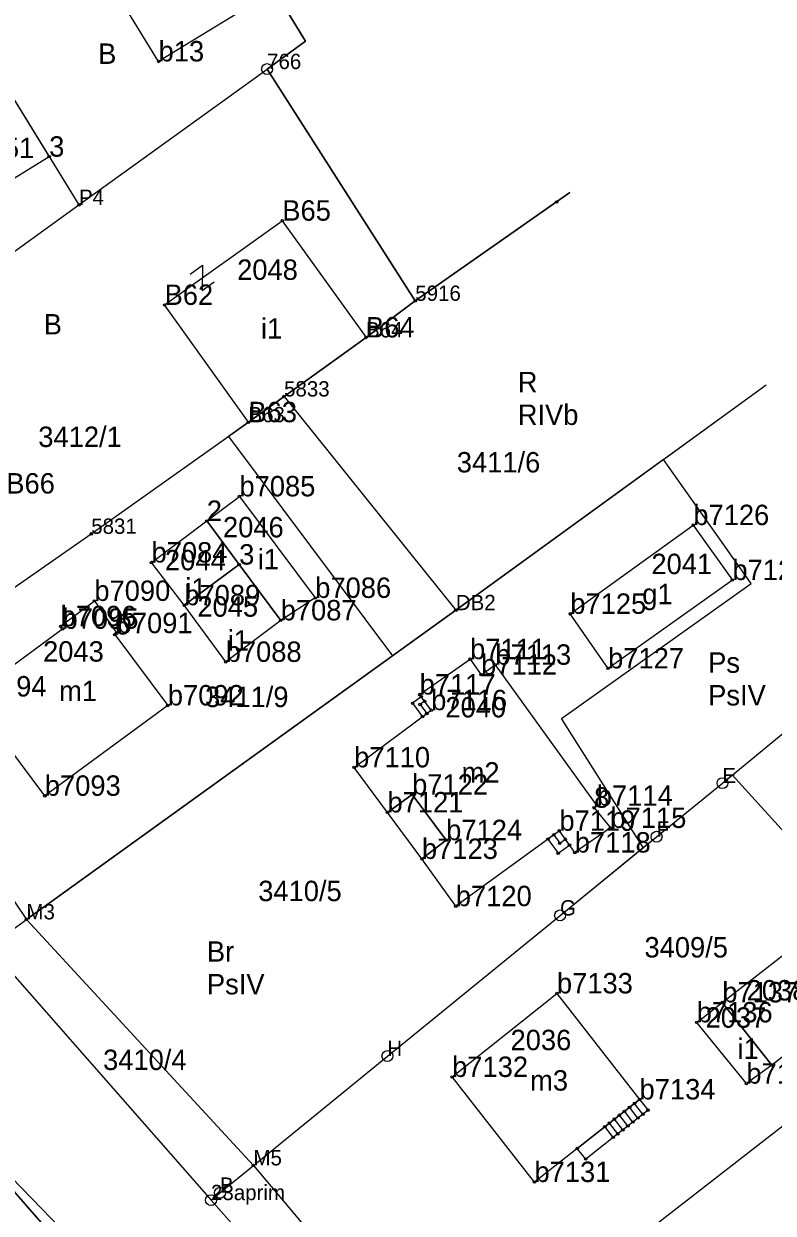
# Model space of a CAD drawing. Extents: x 7492083 to 7492670, y 5466693 to 5467065.
# Drawn here: x 7492206.8 to 7492261.9, y 5466933.4 to 5467020.8 of the extents above; entities that cross this region are included whole.
import ezdxf

# ---------------------------------------------------------------- set-up
doc = ezdxf.new("R2010")
doc.units = 0
for name, color, linetype in [('202-punkt graniczny', 7, 'Continuous'), ('202-punkt graniczny-Atr103', 7, 'Continuous'), ('203-punkt graniczny', 7, 'Continuous'), ('203-punkt graniczny-Atr103', 7, 'Continuous'), ('209-oznaczenie konturu klasyfikacyjnego', 7, 'Continuous'), ('210-oznaczenie konturu użytku gruntowego', 7, 'Continuous'), ('211-numer działki ewidencyjnej', 7, 'Continuous'), ('217-kontur klasyfikacyjny', 7, 'Continuous'), ('218-kontur użytku gruntowego', 7, 'Continuous'), ('219-działka ewidencyjna', 7, 'Continuous'), ('312-budynek ewidencyjny', 7, 'Continuous'), ('312-oznaczenie budynku ewidencyjnego', 7, 'Continuous'), ('312-oznaczenie budynku ewidencyjnego-Atr117', 7, 'Continuous'), ('352-schody', 7, 'Continuous'), ('991-Przehaczenie', 7, 'Continuous'), ('blok - nawis', 7, 'Continuous'), ('Punkt budynku', 7, 'Continuous'), ('Punkt budynku-Atr103', 7, 'Continuous'), ('Punkt budynku-Atr104', 7, 'Continuous')]:
    doc.layers.add(name, color=color, linetype=linetype)

# ---------------------------------------------------------------- blocks, each defined once
blk = doc.blocks.new('203')
blk.add_circle((0, 0), 0.09)
blk = doc.blocks.new('202')
blk.add_circle((0, 0), 0.4)
blk = doc.blocks.new('PUNKTBUD')
blk.add_circle((0, 0), 0.09)
blk = doc.blocks.new('991')
for p, q in [((-0.55, 0.75), (0.55, 0.75)), ((0.55, 0.75), (-0.55, -0.75)), ((-0.55, -0.75), (0.55, -0.75))]:
    blk.add_line(p, q)

msp = doc.modelspace()

# ---------------------------------------------------------------- linework, layer by layer
at = {"layer": '217-kontur klasyfikacyjny'}
for points in [[(7492215.82, 5467038.58), (7492227.5, 5467019.53)], [(7492227.5, 5467019.53), (7492224.67, 5467017.48)], [(7492224.67, 5467017.48), (7492235.56, 5467000.45)], [(7492246.921, 5467008.402), (7492245.94, 5467007.72)], [(7492245.94, 5467007.72), (7492235.56, 5467000.45)], [(7492235.56, 5467000.45), (7492231.94, 5466997.76)], [(7492231.94, 5466997.76), (7492225.92, 5466993.42)], [(7492253.8, 5466988.8), (7492261.338, 5466994.271)], [(7492225.92, 5466993.42), (7492223.3, 5466991.53)], [(7492223.3, 5466991.53), (7492221.84, 5466990.49)], [(7492221.84, 5466990.49), (7492233.88, 5466974.36)], [(7492253.8, 5466988.8), (7492238.54, 5466977.72)], [(7492260.25, 5466979.69), (7492253.8, 5466988.8)], [(7492246.3, 5466969.77), (7492260.25, 5466979.69)], [(7492238.54, 5466977.72), (7492233.88, 5466974.36)], [(7492233.88, 5466974.36), (7492206.99, 5466955)], [(7492252.31, 5466960.27), (7492246.3, 5466969.77)], [(7492258.13, 5466965.01), (7492258.85, 5466965.61)], [(7492258.85, 5466965.61), (7492266.79, 5466956.88)], [(7492253.29, 5466961.07), (7492258.13, 5466965.01)], [(7492246.2, 5466955.29), (7492252.31, 5466960.27)], [(7492252.31, 5466960.27), (7492253.29, 5466961.07)], [(7492233.51, 5466944.96), (7492246.2, 5466955.29)], [(7492206.99, 5466955), (7492223.67, 5466936.92)], [(7492223.67, 5466936.92), (7492233.51, 5466944.96)]]:
    msp.add_lwpolyline(points, dxfattribs=at)
at = {"layer": '218-kontur użytku gruntowego'}
for points in [[(7492227.5, 5467019.53), (7492215.82, 5467038.58)], [(7492224.67, 5467017.48), (7492227.5, 5467019.53)], [(7492235.56, 5467000.45), (7492224.67, 5467017.48)], [(7492246.921, 5467008.402), (7492245.94, 5467007.72)], [(7492245.94, 5467007.72), (7492235.56, 5467000.45)], [(7492235.56, 5467000.45), (7492231.94, 5466997.76)], [(7492231.94, 5466997.76), (7492225.92, 5466993.42)], [(7492253.8, 5466988.8), (7492261.338, 5466994.271)], [(7492225.92, 5466993.42), (7492223.3, 5466991.53)], [(7492223.3, 5466991.53), (7492221.84, 5466990.49)], [(7492221.84, 5466990.49), (7492233.88, 5466974.36)], [(7492253.8, 5466988.8), (7492238.54, 5466977.72)], [(7492260.25, 5466979.69), (7492253.8, 5466988.8)], [(7492246.3, 5466969.77), (7492260.25, 5466979.69)], [(7492238.54, 5466977.72), (7492233.88, 5466974.36)], [(7492233.88, 5466974.36), (7492206.99, 5466955)], [(7492195.51, 5466972.02), (7492206.99, 5466955)], [(7492252.31, 5466960.27), (7492246.3, 5466969.77)], [(7492258.13, 5466965.01), (7492258.85, 5466965.61)], [(7492258.85, 5466965.61), (7492266.79, 5466956.88)], [(7492253.29, 5466961.07), (7492258.13, 5466965.01)], [(7492246.2, 5466955.29), (7492252.31, 5466960.27)], [(7492252.31, 5466960.27), (7492253.29, 5466961.07)], [(7492233.51, 5466944.96), (7492246.2, 5466955.29)], [(7492206.99, 5466955), (7492223.67, 5466936.92)], [(7492223.67, 5466936.92), (7492233.51, 5466944.96)], [(7492219.52, 5466919.65), (7492198.51, 5466943.63)], [(7492223.67, 5466936.92), (7492237.56, 5466920.41)]]:
    msp.add_lwpolyline(points, dxfattribs=at)
at = {"layer": '219-działka ewidencyjna'}
for points in [[(7492203.92, 5467018.7), (7492210.85, 5467007.5)], [(7492210.85, 5467007.5), (7492224.67, 5467017.48)], [(7492224.67, 5467017.48), (7492235.56, 5467000.45)], [(7492245.94, 5467007.72), (7492246.921, 5467008.402)], [(7492185.94, 5466989.5), (7492210.85, 5467007.5)], [(7492235.56, 5467000.45), (7492245.94, 5467007.72)], [(7492231.94, 5466997.76), (7492235.56, 5467000.45)], [(7492225.92, 5466993.42), (7492231.94, 5466997.76)], [(7492238.54, 5466977.72), (7492261.338, 5466994.271)], [(7492223.3, 5466991.53), (7492225.92, 5466993.42)], [(7492225.92, 5466993.42), (7492238.54, 5466977.72)], [(7492211.75, 5466983.33), (7492223.3, 5466991.53)], [(7492195.51, 5466972.02), (7492211.75, 5466983.33)], [(7492206.99, 5466955), (7492238.54, 5466977.72)], [(7492195.51, 5466972.02), (7492206.99, 5466955)], [(7492258.13, 5466965.01), (7492264.25, 5466970.06)], [(7492253.29, 5466961.07), (7492258.13, 5466965.01)], [(7492246.2, 5466955.29), (7492253.29, 5466961.07)], [(7492233.51, 5466944.96), (7492246.2, 5466955.29)], [(7492204.2, 5466952.99), (7492206.99, 5466955)], [(7492206.99, 5466955), (7492223.67, 5466936.92)], [(7492204.2, 5466952.99), (7492220.55, 5466934.37)], [(7492237.56, 5466920.41), (7492278.95, 5466952.56)], [(7492223.67, 5466936.92), (7492233.51, 5466944.96)], [(7492198.51, 5466943.63), (7492260.93, 5466879.15)], [(7492198.51, 5466943.63), (7492219.52, 5466919.65)], [(7492221.21, 5466934.91), (7492223.67, 5466936.92)], [(7492223.67, 5466936.92), (7492237.56, 5466920.41)], [(7492220.55, 5466934.37), (7492221.21, 5466934.91)], [(7492220.55, 5466934.37), (7492234.8, 5466918.26)]]:
    msp.add_lwpolyline(points, dxfattribs=at)
at = {"layer": '312-budynek ewidencyjny'}
for points in [[(7492216.7, 5467018.04), (7492211.32, 5467026.81)], [(7492223.52, 5467022.2), (7492216.7, 5467018.04)], [(7492203.92, 5467018.7), (7492208.66, 5467011.04)], [(7492208.66, 5467011.04), (7492202.65, 5467007.34)], [(7492217.14, 5467000.15), (7492225.79, 5467006.34)], [(7492225.79, 5467006.34), (7492231.94, 5466997.76)], [(7492223.3, 5466991.53), (7492217.14, 5467000.15)], [(7492231.94, 5466997.76), (7492223.3, 5466991.53)], [(7492220.24, 5466984.28), (7492222.64, 5466986.08)], [(7492222.64, 5466986.08), (7492228.21, 5466978.62)], [(7492216.18, 5466981.22), (7492220.24, 5466984.28)], [(7492220.24, 5466984.28), (7492222.62, 5466981.07)], [(7492222.62, 5466981.07), (7492220.24, 5466984.28)], [(7492246.95, 5466977.45), (7492255.99, 5466983.97)], [(7492255.99, 5466983.97), (7492258.86, 5466979.93)], [(7492218.59, 5466978.08), (7492216.18, 5466981.22)], [(7492222.62, 5466981.07), (7492218.59, 5466978.08)], [(7492218.59, 5466978.08), (7492222.62, 5466981.07)], [(7492222.62, 5466981.07), (7492225.67, 5466976.97)], [(7492225.67, 5466976.97), (7492222.62, 5466981.07)], [(7492258.86, 5466979.93), (7492249.73, 5466973.44)], [(7492228.21, 5466978.62), (7492225.67, 5466976.97)], [(7492209.5, 5466976.54), (7492211.98, 5466978.4)], [(7492211.98, 5466978.4), (7492213.62, 5466976.03)], [(7492221.63, 5466973.92), (7492218.59, 5466978.08)], [(7492225.67, 5466976.97), (7492221.63, 5466973.92)], [(7492249.73, 5466973.44), (7492246.95, 5466977.45)], [(7492202.89, 5466971.38), (7492209.64, 5466976.35)], [(7492209.64, 5466976.35), (7492209.5, 5466976.54)], [(7492213.62, 5466976.03), (7492213.48, 5466975.93)], [(7492213.48, 5466975.93), (7492217.38, 5466970.72)], [(7492235.88, 5466971.52), (7492239.59, 5466974.12)], [(7492239.59, 5466974.12), (7492240.4, 5466972.98)], [(7492240.4, 5466972.98), (7492241.44, 5466973.71)], [(7492241.44, 5466973.71), (7492248.9, 5466963.35)], [(7492208.34, 5466964.08), (7492202.89, 5466971.38)], [(7492236.73, 5466970.37), (7492235.88, 5466971.52)], [(7492217.38, 5466970.72), (7492208.34, 5466964.08)], [(7492231.07, 5466966.17), (7492236.73, 5466970.37)], [(7492233.52, 5466962.86), (7492231.07, 5466966.17)], [(7492235.33, 5466964.17), (7492233.52, 5466962.86)], [(7492237.83, 5466960.82), (7492235.33, 5466964.17)], [(7492248.9, 5466963.35), (7492248.7, 5466963.2)], [(7492248.7, 5466963.2), (7492249.9, 5466961.72)], [(7492246.15, 5466961.51), (7492238.54, 5466955.97)], [(7492247.28, 5466959.91), (7492246.15, 5466961.51)], [(7492249.9, 5466961.72), (7492247.28, 5466959.91)], [(7492236.05, 5466959.44), (7492237.83, 5466960.82)], [(7492238.54, 5466955.97), (7492236.05, 5466959.44)], [(7492258.12, 5466948.9), (7492263.18, 5466952.83)], [(7492238.27, 5466943.42), (7492245.97, 5466949.56)], [(7492245.97, 5466949.56), (7492252.04, 5466941.77)], [(7492256.24, 5466947.43), (7492258.12, 5466948.9)], [(7492258.12, 5466948.9), (7492261.75, 5466944.29)], [(7492261.75, 5466944.29), (7492258.12, 5466948.9)], [(7492266.73, 5466948.13), (7492261.75, 5466944.29)], [(7492259.89, 5466942.93), (7492256.24, 5466947.43)], [(7492261.75, 5466944.29), (7492259.89, 5466942.93)], [(7492244.32, 5466935.7), (7492238.27, 5466943.42)], [(7492252.04, 5466941.77), (7492244.32, 5466935.7)]]:
    msp.add_lwpolyline(points, dxfattribs=at)
at = {"layer": '352-schody'}
for p, q in [((7492236, 5466971.36), (7492235.36, 5466970.88)), ((7492235.36, 5466970.88), (7492236.09, 5466969.89)), ((7492236.24, 5466971.03), (7492235.92, 5466970.79)), ((7492235.92, 5466970.79), (7492236.41, 5466970.13)), ((7492236.73, 5466970.37), (7492236, 5466971.36)), ((7492236.09, 5466969.89), (7492236.73, 5466970.37)), ((7492246.15, 5466961.51), (7492245.31, 5466960.9)), ((7492245.73, 5466961.21), (7492246.17, 5466960.59)), ((7492246.89, 5466960.46), (7492246.15, 5466961.51)), ((7492245.31, 5466960.9), (7492246.06, 5466959.86)), ((7492246.06, 5466959.86), (7492246.89, 5466960.46)), ((7492246.17, 5466960.59), (7492246.59, 5466960.89)), ((7492247.46, 5466938.17), (7492252.04, 5466941.77)), ((7492251.92, 5466940.4), (7492251.3, 5466941.19)), ((7492252.29, 5466940.69), (7492251.67, 5466941.48)), ((7492252.04, 5466941.77), (7492252.66, 5466940.98)), ((7492252.66, 5466940.98), (7492250.11, 5466938.98)), ((7492250.81, 5466939.53), (7492250.19, 5466940.32)), ((7492251.18, 5466939.82), (7492250.56, 5466940.61)), ((7492251.55, 5466940.11), (7492250.93, 5466940.9)), ((7492250.11, 5466938.98), (7492249.49, 5466939.77)), ((7492250.44, 5466939.24), (7492249.82, 5466940.03)), ((7492250.11, 5466938.98), (7492248.08, 5466937.39)), ((7492248.08, 5466937.39), (7492247.46, 5466938.17))]:
    msp.add_line(p, q, dxfattribs=at)
at = {"layer": 'blok - nawis'}
msp.add_lwpolyline([(7492233.52, 5466962.86), (7492235.33, 5466964.17), (7492237.83, 5466960.82), (7492236.05, 5466959.44)], close=True, dxfattribs=at)

# ---------------------------------------------------------------- block references
at = {"layer": '202-punkt graniczny'}
for p in [(7492224.67, 5467017.48), (7492258.13, 5466965.01), (7492253.29, 5466961.07), (7492246.2, 5466955.29), (7492233.51, 5466944.96), (7492221.21, 5466934.91), (7492220.55, 5466934.37)]:
    msp.add_blockref('202', p, dxfattribs=at)
at = {"layer": '203-punkt graniczny'}
for p in [(7492210.85, 5467007.5), (7492245.94, 5467007.72), (7492235.56, 5467000.45), (7492231.94, 5466997.76), (7492225.92, 5466993.42), (7492223.3, 5466991.53), (7492211.75, 5466983.33), (7492238.54, 5466977.72), (7492206.99, 5466955), (7492223.67, 5466936.92)]:
    msp.add_blockref('203', p, dxfattribs=at)
at = {"layer": '991-Przehaczenie', "rotation": 35.586}
msp.add_blockref('991', (7492219.91, 5467002.13), dxfattribs=at)
at = {"layer": 'Punkt budynku'}
for p in [(7492216.7, 5467018.04), (7492208.66, 5467011.04), (7492225.79, 5467006.34), (7492217.14, 5467000.15), (7492231.94, 5466997.76), (7492223.3, 5466991.53), (7492222.64, 5466986.08), (7492220.24, 5466984.28), (7492255.99, 5466983.97), (7492216.18, 5466981.22), (7492222.62, 5466981.07), (7492258.86, 5466979.93), (7492228.21, 5466978.62), (7492211.98, 5466978.4), (7492218.59, 5466978.08), (7492225.67, 5466976.97), (7492246.95, 5466977.45), (7492209.5, 5466976.54), (7492209.64, 5466976.35), (7492213.48, 5466975.93), (7492213.62, 5466976.03), (7492221.63, 5466973.92), (7492239.59, 5466974.12), (7492241.44, 5466973.71), (7492249.73, 5466973.44), (7492240.4, 5466972.98), (7492217.38, 5466970.72), (7492235.36, 5466970.88), (7492235.88, 5466971.52), (7492235.92, 5466970.79), (7492236, 5466971.36), (7492236.24, 5466971.03), (7492236.09, 5466969.89), (7492236.41, 5466970.13), (7492236.73, 5466970.37), (7492231.07, 5466966.17), (7492208.34, 5466964.08), (7492235.33, 5466964.17), (7492233.52, 5466962.86), (7492248.7, 5466963.2), (7492248.9, 5466963.35), (7492245.73, 5466961.21), (7492246.15, 5466961.51), (7492249.9, 5466961.72), (7492237.83, 5466960.82), (7492245.31, 5466960.9), (7492246.17, 5466960.59), (7492246.59, 5466960.89), (7492246.89, 5466960.46), (7492236.05, 5466959.44), (7492246.06, 5466959.86), (7492247.28, 5466959.91), (7492238.54, 5466955.97), (7492245.97, 5466949.56), (7492258.12, 5466948.9), (7492256.24, 5466947.43), (7492261.75, 5466944.29), (7492238.27, 5466943.42), (7492259.89, 5466942.93), (7492251.3, 5466941.19), (7492251.67, 5466941.48), (7492252.04, 5466941.77), (7492252.66, 5466940.98), (7492250.19, 5466940.32), (7492250.56, 5466940.61), (7492250.93, 5466940.9), (7492251.55, 5466940.11), (7492251.92, 5466940.4), (7492252.29, 5466940.69), (7492249.49, 5466939.77), (7492249.82, 5466940.03), (7492250.44, 5466939.24), (7492250.81, 5466939.53), (7492251.18, 5466939.82), (7492250.11, 5466938.98), (7492247.46, 5466938.17), (7492248.08, 5466937.39), (7492244.32, 5466935.7)]:
    msp.add_blockref('PUNKTBUD', p, dxfattribs=at)

# ---------------------------------------------------------------- texts
at = {"layer": '202-punkt graniczny-Atr103'}
for s, p in [('766', (7492224.67, 5467017.48)), ('E', (7492258.13, 5466965.01)), ('F', (7492253.29, 5466961.07)), ('G', (7492246.2, 5466955.29)), ('H', (7492233.51, 5466944.96)), ('B', (7492221.21, 5466934.91)), ('23aprim', (7492220.55, 5466934.37))]:
    msp.add_text(s, height=1.125, dxfattribs=at).set_placement(p)
at = {"layer": '203-punkt graniczny-Atr103'}
for s, p in [('P4', (7492210.85, 5467007.5)), ('5916', (7492235.56, 5467000.45)), ('B64', (7492231.94, 5466997.76)), ('5833', (7492225.92, 5466993.42)), ('B63', (7492223.3, 5466991.53)), ('5831', (7492211.75, 5466983.33)), ('DB2', (7492238.54, 5466977.72)), ('M3', (7492206.99, 5466955)), ('M5', (7492223.67, 5466936.92))]:
    msp.add_text(s, height=1.125, dxfattribs=at).set_placement(p)
at = {"layer": '209-oznaczenie konturu klasyfikacyjnego'}
for s, p in [('RIVb', (7492243.09, 5466991.33)), ('PsIV', (7492257.08, 5466970.72)), ('PsIV', (7492220.25, 5466949.49))]:
    msp.add_text(s, height=1.5, dxfattribs=at).set_placement(p)
at = {"layer": '210-oznaczenie konturu użytku gruntowego'}
for s, p in [('B', (7492212.26, 5467017.86)), ('B', (7492208.26, 5466997.98)), ('R', (7492243.09, 5466993.73)), ('Ps', (7492257.08, 5466973.12)), ('Br', (7492220.25, 5466951.89))]:
    msp.add_text(s, height=1.5, dxfattribs=at).set_placement(p)
at = {"layer": '211-numer działki ewidencyjnej'}
for s, p in [('3412/1', (7492207.86, 5466989.71)), ('3411/6', (7492238.61, 5466987.84)), ('3411/9', (7492220.11, 5466970.6)), ('3410/5', (7492224.02, 5466956.34)), ('3409/5', (7492252.4, 5466952.2)), ('3410/4', (7492212.62, 5466943.93))]:
    msp.add_text(s, height=1.5, dxfattribs=at).set_placement(p)
at = {"layer": '312-oznaczenie budynku ewidencyjnego'}
for s, p in [('2051', (7492203.1, 5467010.94)), ('2048', (7492222.47, 5467001.99)), ('2046', (7492221.43, 5466983.07)), ('2044', (7492217.17, 5466980.65)), ('2041', (7492252.91, 5466980.37)), ('2045', (7492219.55, 5466977.24)), ('2043', (7492208.21, 5466973.94)), ('2040', (7492237.77, 5466969.84)), ('2038', (7492259.91, 5466949.04)), ('2037', (7492256.89, 5466947.04)), ('2036', (7492242.56, 5466945.39))]:
    msp.add_text(s, height=1.5, dxfattribs=at).set_placement(p)
at = {"layer": '312-oznaczenie budynku ewidencyjnego-Atr117'}
for s, p in [('i1', (7492224.222, 5466997.67)), ('i1', (7492223.98, 5466980.72)), ('i1', (7492218.66, 5466978.57)), ('g1', (7492252.239, 5466978.16)), ('i1', (7492221.78, 5466974.75)), ('m1', (7492209.39, 5466971.04)), ('m2', (7492238.966, 5466965.05)), ('i1', (7492259.24, 5466944.75)), ('m3', (7492244, 5466942.42))]:
    msp.add_text(s, height=1.5, dxfattribs=at).set_placement(p)
at = {"layer": 'Punkt budynku-Atr103'}
for s, p in [('b13', (7492216.7, 5467018.04)), ('B65', (7492225.79, 5467006.34)), ('B62', (7492217.14, 5467000.15)), ('B64', (7492231.94, 5466997.76)), ('B63', (7492223.3, 5466991.53)), ('B66', (7492205.51, 5466986.29)), ('b7085', (7492222.64, 5466986.08)), ('b7126', (7492255.99, 5466983.97)), ('b7084', (7492216.18, 5466981.22)), ('b7128', (7492258.86, 5466979.93)), ('b7090', (7492211.98, 5466978.4)), ('b7089', (7492218.59, 5466978.08)), ('b7086', (7492228.21, 5466978.62)), ('b7125', (7492246.95, 5466977.45)), ('b7096', (7492209.5, 5466976.54)), ('b7095', (7492209.64, 5466976.35)), ('b7087', (7492225.67, 5466976.97)), ('b7091', (7492213.62, 5466976.03)), ('b7088', (7492221.63, 5466973.92)), ('b7111', (7492239.59, 5466974.12)), ('b7113', (7492241.44, 5466973.71)), ('b7112', (7492240.4, 5466972.98)), ('b7127', (7492249.73, 5466973.44)), ('b7094', (7492202.89, 5466971.38)), ('b7117', (7492235.88, 5466971.52)), ('b7092', (7492217.38, 5466970.72)), ('b7116', (7492236.73, 5466970.37)), ('b7110', (7492231.07, 5466966.17)), ('b7093', (7492208.34, 5466964.08)), ('b7122', (7492235.33, 5466964.17)), ('b7114', (7492248.9, 5466963.35)), ('b7121', (7492233.52, 5466962.86)), ('b7119', (7492246.15, 5466961.51)), ('b7115', (7492249.9, 5466961.72)), ('b7124', (7492237.83, 5466960.82)), ('b7118', (7492247.28, 5466959.91)), ('b7123', (7492236.05, 5466959.44)), ('b7120', (7492238.54, 5466955.97)), ('b7133', (7492245.97, 5466949.56)), ('b7137', (7492258.12, 5466948.9)), ('b7136', (7492256.24, 5466947.43)), ('b7132', (7492238.27, 5466943.42)), ('b7135', (7492259.89, 5466942.93)), ('b7134', (7492252.04, 5466941.77)), ('b7131', (7492244.32, 5466935.7))]:
    msp.add_text(s, height=1.5, dxfattribs=at).set_placement(p)
at = {"layer": 'Punkt budynku-Atr104'}
for s, p in [('3', (7492208.66, 5467011.04)), ('2', (7492220.24, 5466984.28)), ('3', (7492222.62, 5466981.07)), ('6', (7492213.48, 5466975.93)), ('8', (7492248.7, 5466963.2))]:
    msp.add_text(s, height=1.5, dxfattribs=at).set_placement(p)

doc.saveas('drawing.dxf')
